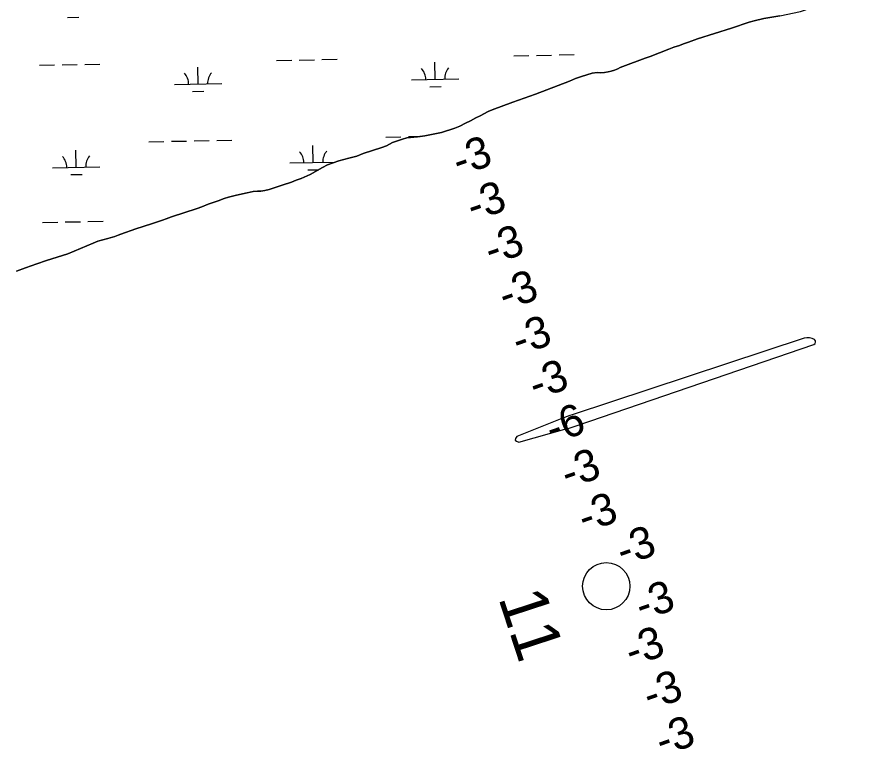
# Model space of a CAD drawing. Extents: x 3989314 to 4027622, y 243956 to 270014.
# Drawn here: x 3999415 to 4001232, y 256557 to 258108 of the extents above; entities that cross this region are included whole.
import ezdxf

# ---------------------------------------------------------------- set-up
doc = ezdxf.new("R2010")
doc.units = 0
for name, color, linetype in [('V-RIVR-EDGE', 7, 'Continuous'), ('V-RIVR-IDEN', 7, 'Continuous'), ('V-RIVR-MILE', 7, 'Continuous'), ('V-RIVR-RANG', 7, 'Continuous'), ('V-TOPO-MINR', 7, 'Continuous'), ('V-WETL-SWMP', 7, 'Continuous')]:
    doc.layers.add(name, color=color, linetype=linetype)

msp = doc.modelspace()

# ---------------------------------------------------------------- linework, layer by layer
at = {"layer": 'V-RIVR-EDGE'}
for points in [[(4000824.7, 258051), (4000835.4, 258055.1), (4000854.1, 258061.9), (4000926.1, 258084.2), (4000939.1, 258088.5), (4000950.8, 258092.9), (4000963.5, 258097.3), (4000974.6, 258100.3), (4000994.5, 258105), (4001011.8, 258107.6), (4001029, 258110.7), (4001072.5, 258119.5), (4001083.1, 258123.3), (4001093, 258127.2), (4001105.6, 258132.8), (4001116.3, 258138.5), (4001125.1, 258142.3), (4001135.2, 258146), (4001144.3, 258148.7), (4001161.9, 258152.8), (4001169.6, 258154.7), (4001186.6, 258159.5), (4001194.4, 258162.9), (4001244.3, 258182.7)], [(3999606.1, 257639.2), (3999621, 257643.6), (3999628.6, 257646.2), (3999634, 257648.4), (3999665.7, 257659.8), (3999698.8, 257670.3), (3999722.1, 257678.1), (3999730.1, 257681.1), (3999741.1, 257684.9), (3999795.3, 257702.5), (3999805.5, 257706.6), (3999818.9, 257711.8), (3999839.9, 257719.4), (3999852.8, 257723.8), (3999861.5, 257726.5), (3999878.5, 257731.3), (3999901.3, 257735.9), (3999914.1, 257738.8), (3999923.2, 257739.4), (3999930.5, 257739.7), (3999938.4, 257740.7), (3999948.1, 257743.1), (3999975.2, 257751.9), (3999995, 257758.8), (4000004.9, 257762.6), (4000015.9, 257766.4), (4000034.9, 257774.6), (4000060.9, 257789.8), (4000071.2, 257795), (4000083.6, 257799.8), (4000095.2, 257803.7), (4000116.8, 257809.1), (4000133.3, 257813.6), (4000146.6, 257819), (4000186.2, 257832), (4000196, 257835.8), (4000209.2, 257842.3), (4000219.5, 257846.2), (4000229.9, 257849.6), (4000239.6, 257852.2), (4000247.3, 257853.4), (4000262.1, 257854.7), (4000277.6, 257856.8), (4000312.8, 257863.4), (4000340.9, 257872.6), (4000351.5, 257877.3), (4000363.5, 257883.1), (4000374.2, 257888.4), (4000385, 257894.6), (4000394.2, 257899.1), (4000411.5, 257908.3), (4000420.2, 257911.9), (4000463.6, 257927.9), (4000511.8, 257945), (4000583.3, 257972.3), (4000596.3, 257977.6), (4000608.9, 257982), (4000631.8, 257989), (4000642.2, 257990.5), (4000649.2, 257990), (4000657.4, 257990.4), (4000665.3, 257991.8), (4000671.8, 257993.5), (4000678.6, 257995.8), (4000685.5, 257998.6), (4000691.1, 258001.4), (4000696.2, 258003.6), (4000744, 258021), (4000754.1, 258024.5), (4000793.5, 258040.3), (4000804.3, 258044.1), (4000816, 258047.9), (4000824.7, 258051)], [(3999412.9, 257570.1), (3999432.3, 257577.5), (3999456.2, 257585.9), (3999476.7, 257592.8), (3999521.8, 257607), (3999575.1, 257629.4), (3999585.5, 257633.4), (3999606.1, 257639.2)]]:
    msp.add_lwpolyline(points, dxfattribs=at)
at = {"layer": 'V-RIVR-MILE'}
msp.add_circle((4000661.4, 256903.6), 50, dxfattribs=at)
at = {"layer": 'V-TOPO-MINR'}
msp.add_lwpolyline([(4000468.5, 257212.8), (4000471.2, 257210.4), (4000476.1, 257208.7), (4000574, 257235.6), (4000580.4, 257237.4), (4000586.9, 257239.3), (4000593.3, 257241.3), (4000599.6, 257243.5), (4001100.6, 257415.2), (4001103.2, 257417.5), (4001104.5, 257420), (4001103.9, 257422.7), (4001101.9, 257425.6), (4001096.8, 257428.1), (4001091.5, 257429.5), (4001086, 257429.5), (4001080.5, 257428.5), (4000589.5, 257266.5), (4000584, 257264.6), (4000578.4, 257262.6), (4000572.9, 257260.6), (4000567.4, 257258.5), (4000472.1, 257220.7), (4000469.2, 257216.4), (4000468.5, 257212.8)], dxfattribs=at)
at = {"layer": 'V-WETL-SWMP'}
for p, q in [((3999521.2, 258107.1), (3999545.2, 258107.6)), ((4000513.4, 258026.9), (4000545.4, 258027.5)), ((4000561.4, 258027.9), (4000593.4, 258028.5)), ((3999963.6, 258015.9), (3999995.6, 258016.6)), ((4000011.6, 258016.9), (4000043.6, 258017.5)), ((4000059.6, 258017.9), (4000091.6, 258018.5)), ((4000299.3, 257976.2), (4000298.6, 258012.2)), ((4000465.4, 258025.9), (4000497.4, 258026.6)), ((3999461.8, 258005.9), (3999493.8, 258006.6)), ((3999509.8, 258006.9), (3999541.8, 258007.5)), ((3999557.8, 258007.9), (3999589.8, 258008.5)), ((3999797.5, 257966.2), (3999796.8, 258002.2)), ((4000249.3, 257975.2), (4000349.3, 257977.2)), ((3999747.5, 257965.2), (3999847.5, 257967.2)), ((4000287.6, 257960.5), (4000311.6, 257961)), ((3999785.8, 257950.5), (3999809.8, 257951)), ((3999741.1, 257845), (3999773.1, 257845.6)), ((3999789.1, 257845.9), (3999821.1, 257846.6)), ((3999837.1, 257846.9), (3999869.1, 257847.5)), ((4000194.9, 257854), (4000226.9, 257854.7)), ((4000242.9, 257855), (4000267.5, 257855.5)), ((3999693.1, 257844), (3999725.1, 257844.7)), ((4000041.3, 257800.2), (4000040.6, 257836.2)), ((3999539.5, 257790.2), (3999538.8, 257826.2)), ((3999489.6, 257789.2), (3999589.5, 257791.2)), ((3999991.4, 257799.2), (4000087.7, 257801.1)), ((3999527.9, 257774.5), (3999551.8, 257775)), ((4000029.7, 257784.5), (4000052.7, 257785)), ((3999468.4, 257673.3), (3999500.4, 257674)), ((3999516.4, 257674.3), (3999548.4, 257674.9)), ((3999564.4, 257675.2), (3999596.4, 257675.9))]:
    msp.add_line(p, q, dxfattribs=at)
for points in [[(4001029, 258110.7), (4001011.8, 258107.6), (4000994.5, 258105), (4000974.6, 258100.3), (4000963.5, 258097.3), (4000950.8, 258092.9), (4000939.1, 258088.5), (4000926.1, 258084.2), (4000854.1, 258061.9), (4000835.4, 258055.1), (4000824.7, 258051), (4000816, 258047.9), (4000804.3, 258044.1), (4000793.5, 258040.3), (4000754.1, 258024.5), (4000744, 258021), (4000696.2, 258003.6), (4000691.1, 258001.4), (4000685.5, 257998.6), (4000678.6, 257995.8), (4000671.8, 257993.5), (4000665.3, 257991.8), (4000657.4, 257990.4), (4000649.2, 257990), (4000642.2, 257990.5), (4000631.8, 257989), (4000608.9, 257982), (4000596.3, 257977.6), (4000583.3, 257972.3), (4000511.8, 257945), (4000463.6, 257927.9), (4000420.2, 257911.9), (4000411.5, 257908.3), (4000394.2, 257899.1), (4000385, 257894.6), (4000374.2, 257888.4), (4000363.5, 257883.1), (4000351.5, 257877.3), (4000340.9, 257872.6), (4000312.8, 257863.4), (4000277.6, 257856.8), (4000262.1, 257854.7), (4000247.3, 257853.4), (4000239.6, 257852.2), (4000229.9, 257849.6), (4000219.5, 257846.2), (4000209.2, 257842.3), (4000196, 257835.8), (4000186.2, 257832), (4000146.6, 257819), (4000133.3, 257813.6), (4000116.8, 257809.1), (4000095.2, 257803.7), (4000083.6, 257799.8), (4000071.2, 257795), (4000060.9, 257789.8), (4000034.9, 257774.6)], [(4000034.9, 257774.6), (4000015.9, 257766.4), (4000004.9, 257762.6), (3999995, 257758.8), (3999975.2, 257751.9), (3999948.1, 257743.1), (3999938.4, 257740.7), (3999930.5, 257739.7), (3999923.2, 257739.4), (3999914.1, 257738.8), (3999901.3, 257735.9), (3999878.5, 257731.3), (3999861.5, 257726.5), (3999852.8, 257723.8), (3999839.9, 257719.4), (3999818.9, 257711.8), (3999805.5, 257706.6), (3999795.3, 257702.5), (3999741.1, 257684.9), (3999730.1, 257681.1), (3999722.1, 257678.1), (3999698.8, 257670.3), (3999665.7, 257659.8), (3999634, 257648.4), (3999628.6, 257646.2), (3999621, 257643.6), (3999606.1, 257639.2), (3999585.5, 257633.4), (3999575.1, 257629.4), (3999521.8, 257607), (3999476.7, 257592.8), (3999456.2, 257585.9), (3999432.3, 257577.5), (3999412.9, 257570.1)]]:
    msp.add_lwpolyline(points, dxfattribs=at)
for centre, start, end in [((4000244.1, 257975.6), 0.3699, 41.9135), ((4000354.6, 257977.8), 140.3699, 181.9135), ((3999742.3, 257965.6), 0.3699, 41.9135), ((3999852.7, 257967.8), 140.3699, 181.9135), ((3999484.3, 257789.6), 0.3699, 41.9135), ((3999594.8, 257791.8), 140.3699, 181.9135), ((3999986.1, 257799.6), 0.3699, 41.9135), ((4000096.6, 257801.8), 140.3699, 181.9135)]:
    msp.add_arc(centre, 35.2, start, end, dxfattribs=at)

# ---------------------------------------------------------------- texts
at = {"layer": 'V-RIVR-IDEN'}
msp.add_text('11', height=100, rotation=288.1185, dxfattribs=at).set_placement((4000432.3, 256879.3))
at = {"layer": 'V-RIVR-RANG'}
for s, p in [('-3', (4000349.3, 257770.2)), ('-3', (4000379.4, 257674.7)), ('-3', (4000417.2, 257582.2)), ('-3', (4000447, 257486.5)), ('-3', (4000475.4, 257390.5)), ('-3', (4000511.2, 257297.2)), ('-6', (4000546.7, 257203.8)), ('-3', (4000579.1, 257109)), ('-3', (4000615.2, 257015.9)), ('-3', (4000696.3, 256945.5)), ('-3', (4000736.2, 256829.6)), ('-3', (4000714.6, 256732.7)), ('-3', (4000752.8, 256640)), ('-3', (4000779, 256543.3))]:
    msp.add_text(s, height=67, rotation=19.2829, dxfattribs=at).set_placement(p)

doc.saveas('drawing.dxf')
